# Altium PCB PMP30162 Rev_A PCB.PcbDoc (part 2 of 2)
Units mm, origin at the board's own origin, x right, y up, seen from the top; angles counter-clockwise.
Board outline 76.83 x 62.23 mm, 2 copper layers (Top Layer, Bottom Layer), stack 1.575 mm thick; 72 components, 34 nets, 157 pads, 116 vias.
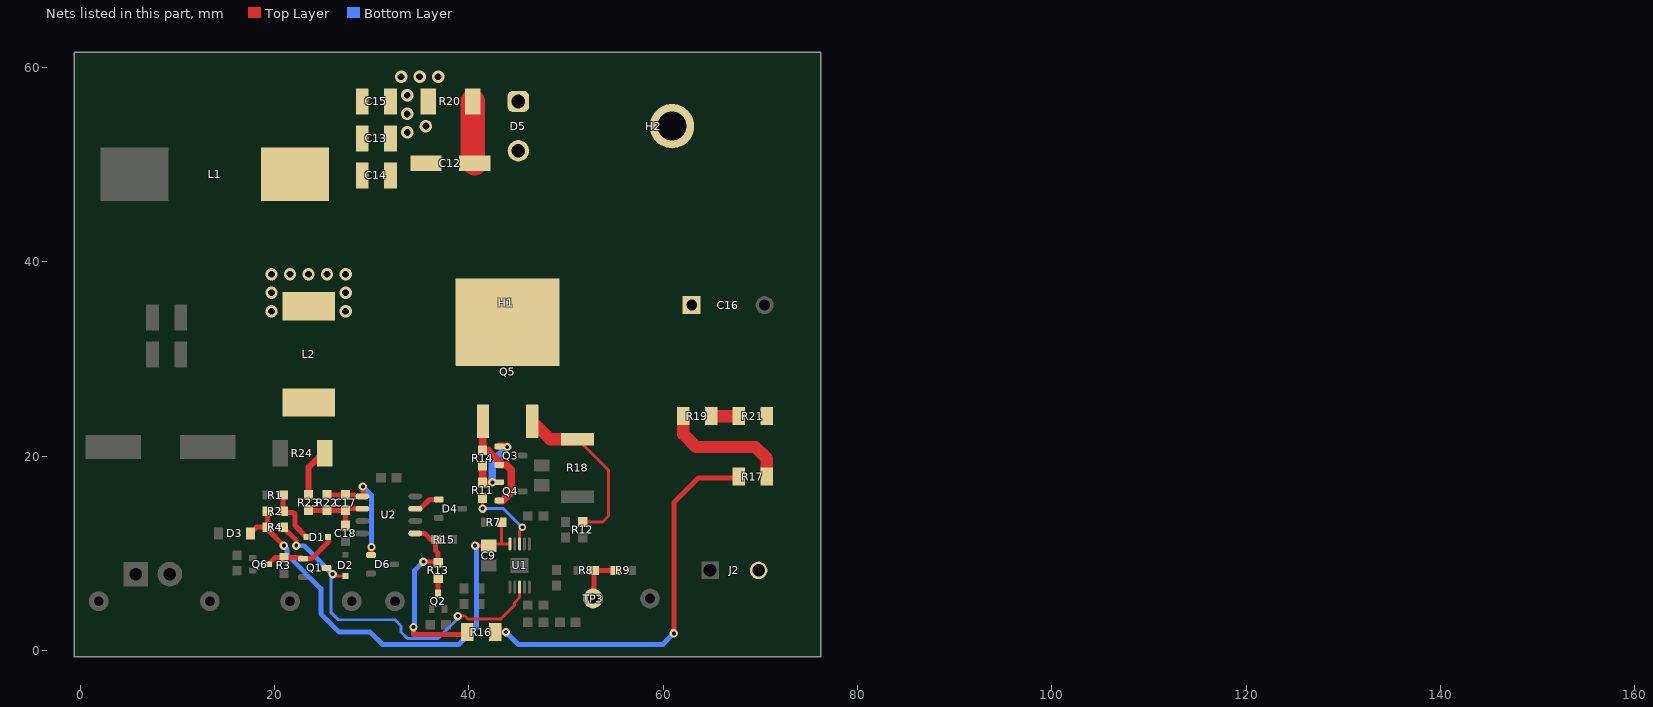
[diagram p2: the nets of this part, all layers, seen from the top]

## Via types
v1: diameter 0.864, hole 0.406, Top Layer to Bottom Layer, 72 vias
v2: diameter 1.27, hole 0.711, Top Layer to Bottom Layer, 37 vias
v3: diameter 0.6, hole 0.3, Top Layer to Bottom Layer, 5 vias
v4: diameter 0.8, hole 0.4, Top Layer to Bottom Layer, tented top, 1 vias
v5: diameter 0.864, hole 0.406, Top Layer to Bottom Layer, tented top, 1 vias

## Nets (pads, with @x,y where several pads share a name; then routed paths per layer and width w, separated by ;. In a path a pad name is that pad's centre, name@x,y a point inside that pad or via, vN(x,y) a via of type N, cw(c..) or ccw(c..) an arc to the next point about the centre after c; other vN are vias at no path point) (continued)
NetC9_1: C9.1 D3.2 R2.2 R4.2 R7.2 U1.10 | length 47.3
  Top Layer w0.305: C9.1@42.037,10.795 42.23,10.988 43.434,10.988 ; R7.2@43.345,13.208 43.345,11.077 43.434,10.988 ; U1.10@44.212,10.988 43.434,10.988
  Top Layer w0.508: D3.2@17.512,12.065 18.147,12.7 R4.2@19.266,12.7 ; R2.2@19.266,14.351 R4.2@19.266,12.7 ; v1(20.955,10.795) 19.266,12.484 R4.2@19.266,12.7 ; v1(40.64,10.795) C9.1@42.037,10.795
  Bottom Layer w0.508: v1(20.955,10.795) 21.285,10.465 21.285,9.855 24.765,6.375 24.765,3.81 26.67,1.905 29.845,1.905 31.115,0.635 33.356,0.635 33.356,0.61 37.104,0.61 37.129,0.635 38.94,0.635 40.718,2.413 40.767,2.413 40.767,10.668 v1(40.64,10.795)
NetC12_1: C12.1 C13.2 C14.2 C15.2 H1.1 L1.2 Q5.4
NetC12_2: C12.2 R20.1 | length 6.4
  Top Layer w2.54: R20.1@40.4,56.515 40.4,50.365 C12.2@40.6,50.165
NetC13_1: C13.1 C14.1 C15.1 D5.3 L2.1 R20.2
  other v2: 19.685,34.925 27.305,34.925 19.685,36.83 27.305,36.83 19.685,38.735 21.59,38.735 23.495,38.735 25.4,38.735 27.305,38.735 33.655,53.34 35.56,53.975 33.655,55.245 33.655,57.15 33.02,59.055 34.925,59.055 36.83,59.055
NetC16_1: C16.1 D5.1 H2.1 J2.2 R21.1
NetC17_1: C17.1 C18.2 R22.2 R23.2 U2.2 | length 7.2
  Top Layer w0.508: R23.2@23.495,14.44 R22.2@25.4,14.44 C17.1@27.305,14.44 ; C18.2@27.305,12.865 C17.1@27.305,14.44 ; U2.2@29.025,14.605 27.47,14.605 C17.1@27.305,14.44
NetC17_2: C17.2 D6.1 R22.1 U2.1 | length 12.2
  Top Layer w0.508: R22.1@25.4,16.04 C17.2@27.305,16.04 27.343,16.002 28.194,16.002 28.321,15.875 U2.1@29.025,15.875 29.083,15.933 v1(29.083,16.891) ; D6.1@29.915,9.84 29.915,10.611 v1(29.972,10.668)
  Bottom Layer w0.508: v1(29.083,16.891) 29.972,16.002 v1(29.972,10.668)
NetD1_1: D1.1 R1.1 R2.1 | length 5.9
  Top Layer w0.508: R1.1@20.866,16.002 R2.1@20.866,14.351 20.993,14.224 21.844,14.224 21.971,14.097 22.098,14.097 22.098,12.87 D1.1@23.284,11.684
NetD1_2: D1.2 Q1.1 Q6.3 R3.2 | length 7.7
  Top Layer w0.508: Q6.3@19.342,8.89 20.015,9.563 R3.2@20.955,9.563 22.826,9.563 Q1.1@22.93,9.459 23.81,9.459 25.527,11.176 25.527,11.641 D1.2@25.484,11.684
NetD2_1: D2.1 Q1.3 R4.1 U1.3 | length 37.1
  Top Layer w0.305: v1(25.965,7.874) 26.176,7.663 D2.1@27.305,7.663 ; v1(38.862,3.556) 39.596,3.556 39.915,3.236 43.241,3.236 44.704,4.699 44.704,4.953 45.212,5.461 U1.3@45.212,6.538
  Top Layer w0.508: R4.1@20.866,12.7 22.225,11.341 v1(22.225,10.795)
  Bottom Layer w0.305: v1(25.965,7.874) 25.781,7.69 25.781,3.937 26.543,3.175 32.385,3.175 33.02,2.54 33.02,1.905 33.655,1.27 36.83,1.27 38.862,3.302 v1(38.862,3.556)
  Bottom Layer w0.508: v1(22.225,10.795) 23.044,10.795 v1(25.965,7.874)
NetD4_1: D4.1 U2.7 | length 2.8
  Top Layer w0.508: U2.7@34.475,14.605 34.991,14.605 35.941,15.555 D4.1@36.9,15.555
NetL2_2: L2.2 R23.1 R24.1 | length 5.1
  Top Layer w0.635: R23.1@23.495,16.04 23.495,18.87 24.945,20.32 R24.1@25.16,20.32
NetQ2_3: Q2.3 R13.1 | length 1.6
  Top Layer w0.508: Q2.3@36.83,5.88 R13.1@36.83,7.455
NetQ3_1: Q3.1 Q4.1 R11.2 R14.1 | length 7.8
  Top Layer w0.762: R14.1@41.402,19.012 R11.2@41.402,17.31 v1(42.418,17.31) ; Q3.1@43.123,21.016 43.881,21.016 v1(43.942,20.955)
  Bottom Layer w0.762: v1(42.418,17.31) 42.418,19.431 v1(43.942,20.955)
NetQ3_2: Q3.2 Q4.2 Q5.1 R14.2 | length 10.9
  Top Layer w0.762: Q5.1@41.432,23.598 41.432,20.642 R14.2@41.402,20.612 41.988,20.612 41.988,20.541 42.448,20.081 42.53,20.081 43.123,19.488 Q3.2@43.123,19.116 43.848,19.116 44.348,18.616 44.348,16.284 43.498,15.433 Q4.2@43.123,15.433
NetQ5_3: Q5.3 R12.2 R18.2 | length 17.5
  Top Layer w0.305: R18.2@51.181,21.746 54.356,18.571 54.356,13.843 53.759,13.246 R12.2@51.722,13.246
  Top Layer w1.27: Q5.3@46.512,23.598 48.364,21.746 R18.2@51.181,21.746
NetR8_2: R8.2 R9.1 TP3.1 | length 5.1
  Top Layer w0.508: TP3.1@52.781,5.359 52.87,5.448 R8.2@52.87,8.255 R9.1@55.08,8.255
NetR11_1: R11.1 U1.8 | length 8
  Top Layer w0.305: v1(41.402,14.605) R11.1@41.402,15.71 ; U1.8@45.212,10.988 45.212,12.319 45.466,12.573 45.593,12.573 45.497,12.669 v4(45.497,12.697)
  Bottom Layer w0.305: v1(41.402,14.605) 43.561,14.605 45.497,12.669 v4(45.497,12.697)
NetR13_2: R13.2 R15.2 R16.2 U2.5 | length 20.1
  Top Layer w0.508: v1(34.29,2.413) 34.29,1.651 39.571,1.651 R16.2@39.825,1.905 ; U2.5@34.475,12.065 35.45,12.065 36.085,11.43 R15.2@36.665,11.43 36.576,11.341 36.576,10.287 36.83,10.033 R13.2@36.83,9.055 36.741,9.144 v1(35.306,9.144)
  Bottom Layer w0.508: v1(34.29,2.413) 34.417,2.54 34.417,8.255 v1(35.306,9.144)
NetR16_1: R16.1 R17.2 | length 40.6
  Top Layer w0.508: R16.1@42.725,1.905 v1(43.815,1.905) ; v1(61.087,1.779) 61.087,15.24 63.627,17.78 67.646,17.78 R17.2@67.765,17.899
  Bottom Layer w0.508: v1(43.815,1.905) 45.085,0.635 59.943,0.635 v1(61.087,1.779)
NetR17_1: R17.1 R19.2 | length 13.4
  Top Layer w1.27: R19.2@62.05,24.13 62.05,22.278 63.373,20.955 69.469,20.955 70.665,19.759 R17.1@70.665,17.899
NetR19_1: R19.1 R21.2 | length 2.8
  Top Layer w1.27: R19.1@64.95,24.13 R21.2@67.765,24.13
pads on no net: H2.0

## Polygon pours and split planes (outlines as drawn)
GND on Top Layer "Top Layer-No Net 2" (solid, pour order 12): 0.635,40.005 75.565,40.005 75.565,0.635 0.635,0.635
NetC16_1 on Top Layer "Bottom Layer-No Net 2" (solid, pour order 10): 43.815,60.96 66.04,60.96 67.945,59.055 67.945,34.29 68.58,33.655 73.025,29.21 75.565,26.67 75.565,6.985 74.295,5.715 67.985,5.715 67.945,5.755 67.905,5.755 67.31,6.35 67.31,13.97 68.58,15.24 71.755,15.24 72.39,15.875 73.025,16.51 73.025,20.62 70.414,23.231 70.414,25.471 69.215,26.67 68.58,27.305 60.325,27.305 58.42,29.21 58.42,47.371 49.617,47.371 48.093,48.895 48.093,52.237 46.355,53.975 44.078,53.975 43.443,54.61 43.443,60.588
NetL2_2 on Top Layer "Bottom Layer-No Net 1" (solid, pour order 8): 17.78,29.845 28.228,29.845 29.498,28.575 29.498,23.783 27.94,22.225 27.94,19.685 26.67,18.415 22.225,18.415 22.225,22.225 21.59,22.86 18.415,22.86 17.78,23.495
NetC13_1 on Top Layer "TOP_LAYER_NETC13_1_P004" (solid, pour order 4): 31.242,60.706 38.354,60.706 38.354,58.547 37.846,58.039 37.846,57.965 37.846,52.324 37.719,52.197 37.592,52.197 33.401,52.197 33.274,52.07 33.147,52.07 33.147,47.498 32.944,47.295 32.83,47.295 31.242,47.295 31.242,60.706
NetC12_1 on Top Layer "Top Layer-No Net 1" (solid, pour order 2): 17.78,60.706 29.972,60.706 30.226,60.452 30.226,60.198 30.226,46.228 30.734,45.72 32.893,45.72 33.909,46.736 33.909,51.308 34.068,51.435 37.973,51.435 38.1,51.308 38.1,47.244 39.497,45.847 40.386,45.847 40.513,45.72 51.308,45.72 52.197,44.831 52.197,44.704 52.197,26.67 52.07,26.543 33.274,26.543 30.48,29.337 30.48,34.925 30.48,41.529 28.829,43.18 18.542,43.18 17.907,43.815 17.907,44.323
NetC4_1 on Top Layer "Top Layer-No Net" (solid, pour order 0): 0.635,60.833 15.24,60.833 15.113,60.706 15.113,39.497 12.954,37.338 9.398,37.338 8.763,36.703 8.382,36.703 8.382,21.082 7.62,20.32 7.62,11.303 7.62,1.778 6.604,0.762 1.27,0.762 0.635,1.397 0.635,1.524
GND on Bottom Layer "Bottom Layer-No Net 3" (solid, pour order 14): 0.635,60.96 75.565,60.96 75.553,60.948 75.553,0.765 75.423,0.635 0.635,0.635
NetC13_1 on Bottom Layer "Bottom Layer-No Net" (solid, pour order 6): 19.558,40.513 19.558,33.909 28.067,33.909 28.067,41.402 34.29,47.625 46.693,47.625 47.328,48.26 47.625,48.26 47.625,50.8 47.625,53.34 41.91,53.34 38.1,57.15 38.1,60.325 34.925,60.325 29.21,60.325 18.923,50.038 18.923,34.544 19.558,33.909

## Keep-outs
Keep-Out Layer:
  text ".Layer_Name" at 14.656,-21.806 h1.52

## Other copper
Top Layer:
  rectangle net NetC13_1: 18.923,33.909 28.067,40.005
  text ".Layer_Name" at 81.534,53.848 h1.52
Bottom Layer:
  text ".Layer_Name" at 81.153,40.767 h1.52

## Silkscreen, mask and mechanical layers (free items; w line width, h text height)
Top Overlay:
  text ".Layer_Name" at 80.772,58.42 h1.52
  text "A" at 73.279,58.039 h1.52 r90
  text "'.PRJ_Number'.PCB_Rev-" at 73.406,44.704 h2.75 r90
  text "+" at 5.08,2.286 h1.52
  text "-" at 8.636,2.286 h1.52
  text "+" at 69.342,2.032 h1.52
  text "-" at 64.262,1.905 h1.52
  text "WARNING: HIGH VOLTAGE" at 74.93,0.635 h1.4 r90
  text "Vin" at 5.715,0.508 h1.52
  text "Vout" at 65.659,0.381 h1.52
Bottom Overlay:
  text ".Layer_Name" at 14.656,-21.806 h1.52
Top Paste:
  text ".Layer_Name" at 14.656,-21.806 h1.52
Bottom Paste:
  text ".Layer_Name" at 14.656,-21.806 h1.52
Top Solder:
  text ".Layer_Name" at 14.656,-21.806 h1.52
  text ".Layer_Name" at 14.656,-21.806 h1.52
Bottom Solder:
  text ".Layer_Name" at 14.656,-21.806 h1.52
Drill Guide:
  text ".Layer_Name" at 14.656,-21.806 h1.52
M1 Board Outline:
  the board outline again, w0.254
  text ".Layer_Name" at 81.026,49.784 h1.52
M2 Board Dimensions:
  rectangle: 3.175,-10.16 12.7,-6.985
  rectangle: 0,-6.985 3.175,-3.81
  lines w0.178: 0,-6.985 25.4,-6.985 ; 3.175,-10.16 3.175,-3.81 ; 6.35,-10.16 6.35,-3.81 ; 12.7,-10.16 12.7,-3.81 ; 19.05,-10.16 19.05,-3.81 ; 0,-10.16 0,-3.81 25.4,-3.81 25.4,-10.16 0,-10.16
  text ".Layer_Name" at 81.026,45.593 h1.52
M3 3D STEP Top:
  text ".Layer_Name" at 14.656,-21.806 h1.52
M4 3D STEP Bottom:
  text ".Layer_Name" at 14.656,-21.806 h1.52
M5 Assembly Top:
  lines w0.254: -7.417,-23.626 160.223,-23.626 ; -7.417,-18.462 160.274,-18.462 ; -7.417,-13.297 -7.417,-28.791 94.31,-28.791 160.274,-28.791 160.274,-13.297 -7.404,-13.297 -7.404,-28.791 32.614,-28.791 ; 55.194,-28.791 55.194,-13.297 ; 87.376,-18.462 87.376,-13.297 ; 108.712,-18.462 108.712,-13.297 ; 124.511,-28.956 124.511,-23.804
  text "COMPONENTS MARKED 'DNP' SHOULD NOT BE POPULATED." at 29.299,-8.09 h1.52
  text "ASSEMBLY VARIANT:" at 29.286,-11.024 h1.52
  text ".VariantName" at 55.601,-11.024 h1.52
  text "PCB VIEWED FROM TOP SIDE" at -5.804,-16.654 h1.52
  text "BOARD #:" at 57.099,-16.654 h1.52
  text ".PRJ_Number" at 70.955,-16.654 h1.52
  text "REV:" at 92.405,-16.654 h1.52
  text ".PCB_Rev" at 99.809,-16.654 h1.52
  text "SVN REV:" at 113.69,-16.654 h1.52
  text ".VersionControl_RevNumber" at 126.543,-16.654 h1.52
  text "TID #:" at 57.099,-21.819 h1.52
  text ".TID" at 70.955,-21.819 h1.52
  text "PLOT NAME =" at -5.804,-27.034 h1.52
  text ".plot_File_Name" at 14.656,-27.034 h1.52
  text "GENERATED    :" at 57.15,-27.034 h1.52
  text ".Print_Date" at 79.235,-27.034 h1.52
  text ".Print_Time" at 97.752,-27.034 h1.52
  text "TEXAS INSTRUMENTS" at 129.87,-27.034 h1.52
M6 Assembly Bottom:
  lines w0.254: -7.429,-18.474 160.261,-18.474 ; -7.379,-23.639 160.261,-23.639 ; 28.334,-28.969 28.334,-23.817 ; 44.133,-18.474 44.133,-13.31 ; 65.468,-18.474 65.468,-13.31 ; 97.65,-28.804 97.65,-13.31 ; 120.231,-28.804 160.249,-28.804 160.249,-13.31 -7.429,-13.31 -7.429,-28.804 58.534,-28.804 160.261,-28.804 160.261,-13.31
  text "COMPONENTS MARKED 'DNP' SHOULD NOT BE POPULATED." at 154.991,-8.077 h1.52
  text ".VariantName" at 128.473,-11.024 h1.52
  text "ASSEMBLY VARIANT:" at 154.864,-11.024 h1.52
  text ".VersionControl_RevNumber" at 26.302,-16.667 h1.52
  text "SVN REV:" at 39.154,-16.667 h1.52
  text ".PCB_Rev" at 53.035,-16.667 h1.52
  text "REV:" at 60.439,-16.667 h1.52
  text ".PRJ_Number" at 81.89,-16.667 h1.52
  text "BOARD #:" at 95.745,-16.667 h1.52
  text "PCB VIEWED FROM BOTTOM SIDE" at 158.648,-16.667 h1.52
  text ".TID" at 81.89,-21.831 h1.52
  text "TID #:" at 95.745,-21.831 h1.52
  text "TEXAS INSTRUMENTS" at 22.974,-27.047 h1.52
  text ".Print_Time" at 55.093,-27.047 h1.52
  text ".Print_Date" at 73.609,-27.047 h1.52
  text "GENERATED    :" at 95.694,-27.047 h1.52
  text ".plot_File_Name" at 138.189,-27.047 h1.52
  text "PLOT NAME =" at 158.648,-27.047 h1.52
M9 Title Sheet:
  drawing of 57 lines, arcs and shapes, not listed
  text "1" at 18.792,204.127 h1.78
  text "2" at 82.182,204.127 h1.78
  text "3" at 145.411,204.127 h1.78
  text "4" at 209.08,204.127 h1.78
  text "5" at 272.555,204.127 h1.78
  text "6" at 336.182,204.127 h1.78
  text "A" at -10.579,175.095 h1.78
  text "A" at 365.341,175.095 h1.78
  text "B" at -10.579,114.643 h1.78
  text "B" at 365.341,114.643 h1.78
  text "C" at -10.579,54.318 h1.78
  text "C" at 365.341,54.318 h1.78
  text "PROJECT TITLE:" at 288.125,7.048 h1.14
  text ".PRJ_Title" at 289.395,3.662 h1.78
  text "DESIGNED FOR:" at 288.125,-0.597 h1.14
  text ".PRJ_Customer" at 289.395,-4.153 h1.78
  text "D" at -10.579,-5.88 h1.78
  text "D" at 365.341,-5.88 h1.78
  text "FILE NAME:" at 288.125,-8.217 h1.14
  text ".PCB_File_Name_No_Path" at 289.395,-11.265 h1.78
  text "Texas Instruments (TI) and/or its licensors do not warrant the accuracy or completeness of this specification" at 161.9,-15.376 h1.14
  text "ENGINEER:" at 288.125,-15.583 h1.14
  text "LAYOUT BY:" at 326.352,-15.583 h1.14
  text "or any information contained therein. TI and/or its licensors do not warrant that this design will meet" at 160.757,-18.237 h1.14
  text ".PRJ_Engineer" at 289.395,-19.52 h1.78
  text ".PCB_Layout" at 327.635,-19.52 h1.78
  text "the specifications, will be suitable for your application or fit for any particular purpose, or will operate in" at 160.757,-21.099 h1.14
  text ".Layer_Name" at 14.656,-21.806 h1.52
  text "ALTIUM DESIGNER VERSION:" at 326.352,-23.457 h1.14
  text "an implementation. TI and/or its licensors do not warrant that the design is production worthy. You should" at 160.757,-23.961 h1.14
  text "completely validate and test your design implementation to confirm the system functionality for your application." at 161.9,-26.822 h1.14
  text ".print_Scale" at 289.395,-26.843 h1.78
  text ".Application_BuildNumber" at 327.635,-26.843 h1.78
  text "1" at 18.792,-32.093 h1.78
  text "2" at 82.182,-32.093 h1.78
  text "3" at 145.411,-32.093 h1.78
  text "4" at 209.08,-32.093 h1.78
  text "5" at 272.555,-32.093 h1.78
  text "6" at 336.182,-32.093 h1.78
M10 Fab Notes:
  drawing of 173 lines, arcs and shapes, not listed
  text "DESIGN INFORMATION" at 314.402,157.505 h1.52
  text "MIN. TRACK WIDTH:" at 298.03,152.933 h1.52
  text "8" at 325.874,152.933 h1.52
  text "MIL" at 329.805,152.933 h1.52
  text "MIN. CLEARANCE:" at 298.03,149.581 h1.52
  text "0.2" at 324.35,149.581 h1.52
  text "mm" at 329.805,149.581 h1.52
  text "MIN. VIA PAD SIZE:" at 298.03,146.228 h1.52
  text "24" at 325.113,146.228 h1.52
  text "MIL" at 329.805,146.228 h1.52
  text "0.05mm (2MIL)" at 315.683,142.628 h1.52
  text "MINIMUM ANNULAR RING" at 289.667,142.52 h1.52
  text "EXTERNAL" at 333.666,142.52 h1.52
  text "PER" at 294.747,139.522 h1.52
  text "IPC-D-275 CLASS 2 LEVEL C" at 300.335,139.522 h1.52
  text "MIL, HOLES" at 338.136,136.67 h1.52
  text "+/-" at 328.168,136.652 h1.52
  text "+/-" at 349.86,136.652 h1.52
  text "REGISTRATION TOLERANCES:" at 289.667,136.525 h1.52
  text "METAL" at 320.142,136.525 h1.52
  text "5" at 334.777,136.525 h1.52
  text "3" at 355.935,136.525 h1.52
  text "MIL" at 358.888,136.525 h1.52
  text "+/-" at 349.86,133.655 h1.52
  text "HOLE SIZE TOLERANCE (UNLESS OTHERWISE SPECIFIED):" at 289.667,133.528 h1.52
  text "3" at 355.935,133.528 h1.52
  text "MIL" at 358.888,133.528 h1.52
  text "MATERIAL:" at 287.768,128.208 h1.52
  text "FR-4 High Tg" at 312.824,124.643 h1.52
  text "FR-408" at 298.462,124.425 h1.52
  text "OTHER" at 336.257,124.425 h1.52
  text "X" at 308.889,124.333 h1.52
  text "62 MIL (1.6mm) +/-10%" at 306.592,120.292 h1.52
  text "THICKNESS:" at 289.667,120.184 h1.52
  text "X" at 303.337,120.184 h1.52
  text "OTHER" at 339.229,120.184 h1.52
  text "TOLERANCE:" at 289.667,116.17 h1.52
  text "X" at 310.986,116.17 h1.52
  text "ANSI IPC-6012 TYPE 3 CLASS 2" at 315.734,116.17 h1.52
  text "OTHER +/-" at 315.734,112.208 h1.52
  text "BOW & TWIST:" at 289.667,108.22 h1.52
  text "X" at 310.986,108.22 h1.52
  text "ANSI IPC-6012 TYPE 3 CLASS 2" at 315.734,108.22 h1.52
  text "OTHER +/-" at 315.734,104.194 h1.52
  text "DRILLING:" at 287.768,100.676 h1.52
  text "REFERENCE:" at 289.667,97.705 h1.52
  text "X" at 306.132,97.705 h1.52
  text "AS SHOWN" at 310.882,97.705 h1.52
  text "X" at 329.018,97.705 h1.52
  text "NC_DRILL FILES" at 332.498,97.705 h1.52
  text "PTH COPPER THICKNESS:" at 289.667,93.691 h1.52
  text "X" at 318.375,93.691 h1.52
  text "20-30 um" at 321.855,93.691 h1.52
  text "OTHER" at 340.067,93.691 h1.52
  text "BOARD FINISH:" at 287.768,89.653 h1.52
  text "SILKSCREEN:" at 291.711,86.656 h1.52
  text "X" at 315.81,86.656 h1.52
  text "TOP" at 319.01,86.656 h1.52
  text "X" at 328.764,86.656 h1.52
  text "BOTTOM" at 331.99,86.656 h1.52
  text "SILKSCREEN COLOR:" at 291.711,82.414 h1.52
  text "X" at 315.783,82.414 h1.52
  text "WHITE" at 319.01,82.414 h1.52
  text "OTHER" at 331.99,82.414 h1.52
  text "X" at 319.111,78.37 h1.52
  text "GREEN" at 322.338,78.37 h1.52
  text "OTHER" at 338.035,78.37 h1.52
  text "SOLDER RESIST COLOR:" at 291.711,78.096 h1.52
  text "X" at 319.111,74.052 h1.52
  text "MATTE" at 322.338,74.052 h1.52
  text "SEMI-GLOSS" at 338.023,74.036 h1.52
  text "IMMERSION GOLD (ENIG)" at 314.718,69.264 h1.52
  text "ENEPIG" at 348.691,69.18 h1.52
  text "SURFACE FINISH:" at 287.768,69.155 h1.52
  text "X" at 309.969,69.155 h1.52
  text "IMM. TIN/SILVER OR EQUIV" at 296.139,65.167 h1.52
  text "OTHER" at 332.498,65.167 h1.52
  text "ARRAY/PANEL:" at 287.768,60.621 h1.52
  text "CUT AND TRIM PER M1 BOARD OUTLINE" at 314.718,60.512 h1.52
  text "N.C. ROUTE" at 314.718,56.658 h1.52
  text "X" at 331.964,56.658 h1.52
  text "V. SCORE" at 336.714,56.658 h1.52
  text "CERTIFICATION:" at 287.768,53.178 h1.52
  text "MATERIALS AND WORKMANSHIP FOR ALL PCBS" at 306.183,53.178 h1.52
  text "TO MEET OR EXCEED THE REQUIREMENTS OF:" at 306.183,50.689 h1.52
  text "X" at 296.696,47.222 h1.52
  text "ANSI IPC-A-600F CLASS ->" at 300.227,47.222 h1.52
  text "X" at 341.859,47.222 h1.52
  text "2" at 344.88,47.222 h1.52
  text "1" at 336.879,47.184 h1.52
  text "3" at 353.872,47.184 h1.52
  text "X" at 317.373,43.171 h1.52
  text "RoHS" at 320.852,43.171 h1.52
  text "OTHER" at 337.22,43.171 h1.52
  text "PER ORDER" at 347.305,43.171 h1.52
  text "ALL BOARDS MUST MEET OR EXCEED UL94-V0 REQUIREMENTS." at 288.468,38.964 h1.52
  text "PCB MUST BEAR THE UL94V-0 UL REGISTERED MATERIAL ID NUMBER" at 288.468,35.916 h1.52
  text "ADDITIONAL REQUIREMENTS:" at 287.768,31.512 h1.52
  text "MICROSECTION:" at 289.667,28.591 h1.52
  text "YES" at 312.673,28.591 h1.52
  text "REQUIRED" at 334.555,24.625 h1.52
  text "BARE BOARD ELEC. TEST:" at 289.667,24.553 h1.52
  text "NONE" at 322.833,24.553 h1.52
  text "X" at 331.329,24.553 h1.52
  text "PER ORDER" at 349.592,24.553 h1.52
  text ".Layer_Name" at 14.656,-21.806 h1.52
M11 Gerber Information:
  lines w0.254: -7.417,-23.626 160.223,-23.626 ; -7.417,-18.462 160.274,-18.462 ; -7.417,-13.297 -7.417,-28.791 94.31,-28.791 160.274,-28.791 160.274,-13.297 -7.404,-13.297 -7.404,-28.791 32.614,-28.791 ; 55.194,-28.791 55.194,-13.297 ; 87.376,-18.462 87.376,-13.297 ; 108.712,-18.462 108.712,-13.297 ; 124.511,-28.956 124.511,-23.804
  text "ALL ARTWORK VIEWED FROM TOP SIDE" at -5.804,-16.654 h1.52
  text "BOARD #:" at 57.099,-16.654 h1.52
  text ".PRJ_Number" at 70.955,-16.654 h1.52
  text "REV:" at 92.405,-16.654 h1.52
  text ".PCB_Rev" at 99.809,-16.654 h1.52
  text "SVN REV:" at 113.69,-16.654 h1.52
  text ".VersionControl_RevNumber" at 126.543,-16.654 h1.52
  text "LAYER NAME =" at -5.804,-21.806 h1.52
  text "TID #:" at 57.099,-21.819 h1.52
  text ".TID" at 70.955,-21.819 h1.52
  text "PLOT NAME =" at -5.804,-27.034 h1.52
  text ".plot_File_Name" at 14.656,-27.034 h1.52
  text "GENERATED    :" at 57.15,-27.034 h1.52
  text ".Print_Date" at 79.235,-27.034 h1.52
  text ".Print_Time" at 97.752,-27.034 h1.52
  text "TEXAS INSTRUMENTS" at 129.87,-27.034 h1.52
M12 Stackup:
  drawing of 191 lines, arcs and shapes, not listed
  text "Layer" at 248.675,198.882 h1.52
  text "Name" at 259.086,198.882 h1.52
  text "Material" at 282.702,198.882 h1.52
  text "Thickness" at 304.54,198.882 h1.52
  text "Constant" at 321.046,198.882 h1.52
  text "Board Layer Stack" at 335.52,198.882 h1.52
  text "1" at 248.675,195.834 h1.52
  text "Top Overlay" at 259.086,195.834 h1.52
  text "2" at 248.675,192.786 h1.52
  text "Top Solder" at 259.086,192.786 h1.52
  text "Solder Resist" at 282.702,192.786 h1.52
  text "0.40mil" at 304.54,192.786 h1.52
  text "3.5" at 321.046,192.786 h1.52
  text "3" at 248.675,189.738 h1.52
  text "Top Layer" at 259.086,189.738 h1.52
  text "Copper" at 282.702,189.738 h1.52
  text "1.40mil" at 304.54,189.738 h1.52
  text "4" at 248.675,186.69 h1.52
  text "Dielectric1" at 259.086,186.69 h1.52
  text "FR-4" at 282.702,186.69 h1.52
  text "59.20mil" at 304.54,186.69 h1.52
  text "4.8" at 321.046,186.69 h1.52
  text "5" at 248.675,183.642 h1.52
  text "Bottom Layer" at 259.086,183.642 h1.52
  text "Copper" at 282.702,183.642 h1.52
  text "1.40mil" at 304.54,183.642 h1.52
  text "6" at 248.675,180.594 h1.52
  text "Bottom Solder" at 259.086,180.594 h1.52
  text "Solder Resist" at 282.702,180.594 h1.52
  text "0.40mil" at 304.54,180.594 h1.52
  text "3.5" at 321.046,180.594 h1.52
  text "7" at 248.675,177.546 h1.52
  text "Bottom Overlay" at 259.086,177.546 h1.52
  text ".Layer_Name" at 14.656,-21.806 h1.52
M13 Component Bodies Top:
  text ".Layer_Name" at 14.656,-21.806 h1.52
M14 Component Bodies Bottom:
  text ".Layer_Name" at 14.656,-21.806 h1.52
M15 Courtyards Top:
  text ".Layer_Name" at 14.656,-21.806 h1.52
M16 Courtyards Bottom:
  text ".Layer_Name" at 14.656,-21.806 h1.52
Drill Drawing:
  circle w0.254: c136.241,76.636 r0.703
  circle w0.254: c136.241,73.475 r0.422
  circle w0.254: c136.241,73.475 r0.703
  lines w0.254: 135.538,54.507 136.241,53.805 136.943,54.507 136.241,55.21 135.538,54.507 ; 135.538,57.317 135.889,57.317 136.241,56.966 136.592,57.317 136.943,57.317 136.592,57.668 136.943,58.02 136.592,58.02 136.241,58.371 135.889,58.02 135.538,58.02 135.889,57.668 135.538,57.317 ; 135.538,60.478 135.889,60.478 135.889,60.127 136.592,60.127 136.592,60.478 136.943,60.478 136.943,61.181 136.592,61.181 136.592,61.532 135.889,61.532 135.889,61.181 135.538,61.181 135.538,60.478 ; 135.538,64.693 136.943,64.693 136.241,63.288 135.538,64.693 ; 135.538,66.45 136.241,66.801 136.943,66.45 136.592,67.152 136.943,67.855 136.241,67.503 135.538,67.855 135.889,67.152 135.538,66.45 ; 135.538,69.611 136.943,69.611 136.943,71.016 135.538,71.016 135.538,69.611 ; 135.538,79.095 136.943,79.095 136.943,80.5 135.538,80.5 135.538,79.095 ; 135.538,83.661 136.943,83.661 136.241,82.256 135.538,83.661 ; 135.819,79.376 136.662,79.376 136.662,80.219 135.819,80.219 135.819,79.376 ; 135.819,83.38 136.662,83.38 136.241,82.537 135.819,83.38
  lines w0.305: 134.264,52.856 216.377,52.856 ; 134.264,84.469 216.377,84.469 ; 142.854,49.695 142.854,87.63 ; 151.29,49.695 151.29,87.63 ; 167.469,49.695 167.469,87.63 ; 174.057,49.695 174.057,87.63 ; 183.593,49.695 183.593,87.63 ; 201.978,49.695 201.978,87.63 ; 134.264,49.695 216.377,49.695 216.377,87.63 134.264,87.63 134.264,49.695
  text "Symbol" at 136.161,85.417 h1.83
  text "Quantity" at 143.802,85.417 h1.83
  text "Finished Hole Size" at 152.238,85.417 h1.83
  text "Plated" at 168.418,85.417 h1.83
  text "Hole Type" at 175.005,85.417 h1.83
  text "Drill Layer Pair" at 184.541,85.417 h1.83
  text "Hole Tolerance" at 202.927,85.417 h1.83
  text "5" at 143.802,82.256 h1.52
  text "11.81mil (0.300mm)" at 152.238,82.256 h1.52
  text "PTH" at 168.418,82.256 h1.52
  text "Round" at 175.005,82.256 h1.52
  text "Top Layer - Bottom Layer" at 184.541,82.256 h1.52
  text "1" at 143.802,79.095 h1.52
  text "15.75mil (0.400mm)" at 152.238,79.095 h1.52
  text "PTH" at 168.418,79.095 h1.52
  text "Round" at 175.005,79.095 h1.52
  text "Top Layer - Bottom Layer" at 184.541,79.095 h1.52
  text "73" at 143.802,75.933 h1.52
  text "16.00mil (0.406mm)" at 152.238,75.933 h1.52
  text "PTH" at 168.418,75.933 h1.52
  text "Round" at 175.005,75.933 h1.52
  text "Top Layer - Bottom Layer" at 184.541,75.933 h1.52
  text "37" at 143.802,72.772 h1.52
  text "28.00mil (0.711mm)" at 152.238,72.772 h1.52
  text "PTH" at 168.418,72.772 h1.52
  text "Round" at 175.005,72.772 h1.52
  text "Top Layer - Bottom Layer" at 184.541,72.772 h1.52
  text "7" at 143.802,69.611 h1.52
  text "40.00mil (1.016mm)" at 152.238,69.611 h1.52
  text "PTH" at 168.418,69.611 h1.52
  text "Round" at 175.005,69.611 h1.52
  text "Top Layer - Bottom Layer" at 184.541,69.611 h1.52
  text "2" at 143.802,66.45 h1.52
  text "43.31mil (1.100mm)" at 152.238,66.45 h1.52
  text "PTH" at 168.418,66.45 h1.52
  text "Round" at 175.005,66.45 h1.52
  text "Top Layer - Bottom Layer" at 184.541,66.45 h1.52
  text "2" at 143.802,63.288 h1.52
  text "50.00mil (1.270mm)" at 152.238,63.288 h1.52
  text "PTH" at 168.418,63.288 h1.52
  text "Round" at 175.005,63.288 h1.52
  text "Top Layer - Bottom Layer" at 184.541,63.288 h1.52
  text "2" at 143.802,60.127 h1.52
  text "51.18mil (1.300mm)" at 152.238,60.127 h1.52
  text "PTH" at 168.418,60.127 h1.52
  text "Round" at 175.005,60.127 h1.52
  text "Top Layer - Bottom Layer" at 184.541,60.127 h1.52
  text "2" at 143.802,56.966 h1.52
  text "55.12mil (1.400mm)" at 152.238,56.966 h1.52
  text "PTH" at 168.418,56.966 h1.52
  text "Round" at 175.005,56.966 h1.52
  text "Top Layer - Bottom Layer" at 184.541,56.966 h1.52
  text "1" at 143.802,53.805 h1.52
  text "118.00mil (2.997mm)" at 152.238,53.805 h1.52
  text "PTH" at 168.418,53.805 h1.52
  text "Round" at 175.005,53.805 h1.52
  text "Top Layer - Bottom Layer" at 184.541,53.805 h1.52
  text "132 Total" at 143.802,50.643 h1.52
  text ".Layer_Name" at 14.656,-21.806 h1.52
M17 Embedded Cavity:
  text ".Layer_Name" at 14.656,-21.806 h1.52
M18 Embedded Assembly:
  text ".Layer_Name" at 14.656,-21.806 h1.52
M19 Embedded Keepout:
  text ".Layer_Name" at 14.656,-21.806 h1.52

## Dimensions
-0.635,-0.635 to -0.635,61.595 on M2 Board Dimensions
-0.635,-0.635 to 76.2,-0.635 on M2 Board Dimensions
0,-10.16 to 25.4,-10.16 on M2 Board Dimensions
